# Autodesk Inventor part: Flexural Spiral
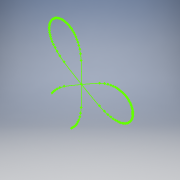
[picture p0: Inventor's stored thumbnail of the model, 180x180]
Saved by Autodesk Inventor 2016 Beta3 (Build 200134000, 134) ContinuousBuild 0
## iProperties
Created: 2008-02
Part Number: Flexural Spiral
Document SubType Name: Modeling
Designer: Autodesk, Inc.
Density: 1 g/cm^3
Material: Generic
Appearance: Default
Author: Autodesk, Inc.
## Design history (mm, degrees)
sketch "Sketch1"
  geometry: 300 further points
  constraints: 300 other
